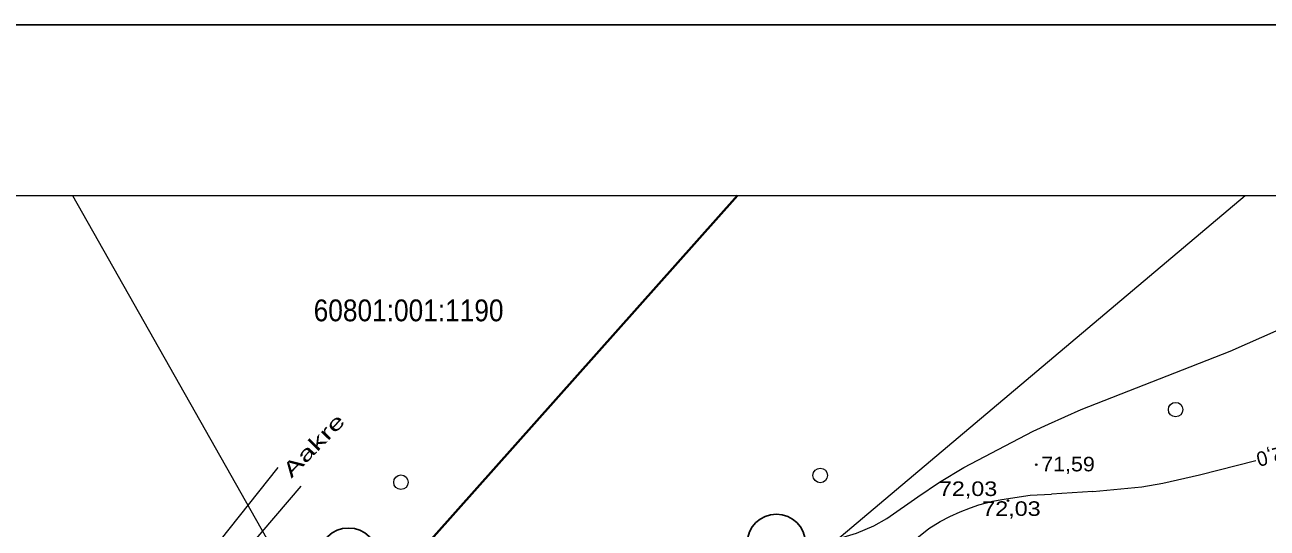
# Model space of a CAD drawing. Extents: x 628176 to 629009, y 6439913 to 6440496.
# Drawn here: x 628361.2 to 628531.9, y 6440426.7 to 6440495.9 of the extents above; entities that cross this region are included whole.
import ezdxf

# ---------------------------------------------------------------- set-up
doc = ezdxf.new("R2010")
doc.units = 0
doc.header["$LTSCALE"] = 0.8
for name, color, linetype, lineweight in [('1', 7, 'Continuous', 13), ('10', 7, 'Continuous', 25), ('20', 7, 'Continuous', 40), ('3', 7, 'Continuous', 13), ('50', 7, 'Continuous', 13), ('6', 7, 'Continuous', 13)]:
    doc.layers.add(name, color=color, linetype=linetype, lineweight=lineweight)
doc.layers.add('23', color=7, linetype='Continuous')

msp = doc.modelspace()

# ---------------------------------------------------------------- hatches: boundary and pattern name
at = {"layer": '1'}
for points in [[(628500.2954, 6440435.4072, 1), (628500.0954, 6440435.4072, 1)], [(628496.4107, 6440430.4615, 1), (628496.2107, 6440430.4615, 1)]]:
    msp.add_hatch(color=256, dxfattribs=at).paths.add_polyline_path(points)

# ---------------------------------------------------------------- linework, layer by layer
for p, q in [((628388, 6440425), (628396, 6440435)), ((628399.08, 6440432.45), (628391.87, 6440423.98))]:
    msp.add_line(p, q, dxfattribs=at)
for centre, radius in [((628519.3622, 6440442.9832), 1), ((628470.5009, 6440433.9348), 1), ((628500.1954, 6440435.4072), 0.1), ((628412.8591, 6440432.9985), 1), ((628496.3107, 6440430.4615), 0.1)]:
    msp.add_circle(centre, radius, dxfattribs=at)
at = {"layer": '10'}
for centre in [(628464.4704, 6440424.6071), (628405.6476, 6440422.6988)]:
    msp.add_circle(centre, 4, dxfattribs=at)
at = {"layer": '20'}
msp.add_line((628410.48, 6440417.82), (628459.12, 6440472.45), dxfattribs=at)
at = {"layer": '3'}
for p, q in [((628522.64, 6440434), (628530.4, 6440435.98)), ((628508, 6440431.7), (628502.32, 6440431.36))]:
    msp.add_line(p, q, dxfattribs=at)
for points in [[(628422, 6440418.57), (628429.42, 6440420), (628438.21, 6440421), (628450.1, 6440422), (628459.07, 6440423), (628466.71, 6440424), (628472.14, 6440425), (628475.51, 6440426), (628477.87, 6440427), (628479.64, 6440428), (628483.9, 6440431), (628486.91, 6440433), (628490.26, 6440435), (628497.84, 6440439), (628499.78, 6440440), (628501.87, 6440441), (628506.4, 6440443), (628526.88, 6440451), (628533.59, 6440454), (628545.23, 6440460), (628547.31, 6440461)], [(628508, 6440431.7), (628514.73, 6440432.35), (628517.61, 6440432.87), (628522.64, 6440434)], [(628456.69, 6440412), (628463.93, 6440413), (628470.35, 6440414), (628473.93, 6440414.73), (628475, 6440415), (628476, 6440415.51), (628477.45, 6440416.53), (628478.52, 6440417.54), (628480, 6440419.63), (628481, 6440421.53), (628481.69, 6440422.69), (628483, 6440424.41), (628484, 6440425.48), (628485.43, 6440426.63), (628487, 6440427.61), (628488.32, 6440428.29), (628489.76, 6440428.94), (628491.16, 6440429.47), (628492.32, 6440429.87), (628493.16, 6440430.12), (628494.23, 6440430.38), (628495.46, 6440430.64), (628499.35, 6440431.22), (628502.32, 6440431.36)]]:
    msp.add_lwpolyline(points, dxfattribs=at)
at = {"layer": '50', "lineweight": 25}
msp.add_lwpolyline([(628178.27, 6440495.9), (629008.51, 6440495.9), (629008.51, 6439918.47), (628178.27, 6439918.47)], close=True, dxfattribs=at)
at = {"layer": '50'}
msp.add_lwpolyline([(628214.18, 6440472.45), (628760.23, 6440472.45), (628760.23, 6440028.67), (628214.18, 6440028.67)], close=True, dxfattribs=at)
at = {"layer": '6'}
for p, q in [((628367.72, 6440472.45), (628398.64, 6440417.82)), ((628464.14, 6440417.8), (628528.94, 6440472.45))]:
    msp.add_line(p, q, dxfattribs=at)

# ---------------------------------------------------------------- texts
at = {"layer": '1', "width": 1.55}
msp.add_text('Aakre', height=2, rotation=45.872, dxfattribs=at).set_placement((628397.8, 6440433.47))
at = {"layer": '1'}
for s, width, p in [('71,59', 1.1, (628500.89, 6440434.49)), ('72,03', 1.2, (628486.81, 6440431.1)), ('72,03', 1.2, (628492.78, 6440428.37))]:
    msp.add_text(s, height=2, dxfattribs=dict(at, width=width)).set_placement(p)
at = {"layer": '23', "width": 0.9}
msp.add_text('60801:001:1190', height=3, dxfattribs=at).set_placement((628400.86, 6440455.13))
at = {"layer": '3'}
msp.add_text('72,0', height=2, rotation=194.352, dxfattribs=at).set_placement((628535.33, 6440438.33))

doc.saveas('drawing.dxf')
